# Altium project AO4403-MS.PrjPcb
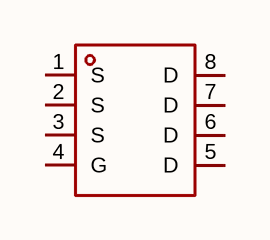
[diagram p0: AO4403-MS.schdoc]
1 sheet, 1 parts. Net scope: global (net labels, ports and power ports of the same name join across sheets).

## Sheet AO4403-MS.schdoc
size 127 x 101 mm

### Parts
Q?  ao4403-ms  [SOP-8_L5.0-W4.0-P1.27-LS6.2-BL]  (value not drawn)

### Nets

Not connected (* = marked no-connect by the designer): Q? 1(S) 2(S) 3(S) 4(G) 5(D) 6(D) 7(D) 8(D)

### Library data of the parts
Q? = ao4403-ms: 数量:1个P沟道;漏源电压(Vdss):30V;连续漏极电流(Id):6A;导通电阻(RDS(on)):48mΩ@10V;耗散功率(Pd):3.1W;阈值电压(Vgs(th)):1.3V;; Manufacturer: MSKSEMI(美森科); AddInBom: yes; ModelId: a3315c1c78f949e6bb82c6eaca1c53c7; ModelName: SOP-8_L5.0-W4.0-H1.8-LS6.2-P1.27; ModelTransform: 244.094,196.85,0,90,0,0,0,0,0; Number: 1个P沟道; Drain to Source Voltage: 30V; Current - Continuous Drain(Id): 6A; Pd - Power Dissipation: 3.1W; Gate Threshold Voltage (Vgs(th)): 1.3V; Gate Charge(Qg): 7nC@4.5V; Input Capacitance(Ciss): 645pF; Reverse Transfer Capacitance (Crss@Vds): 55pF; Output Capacitance(Coss): 80pF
